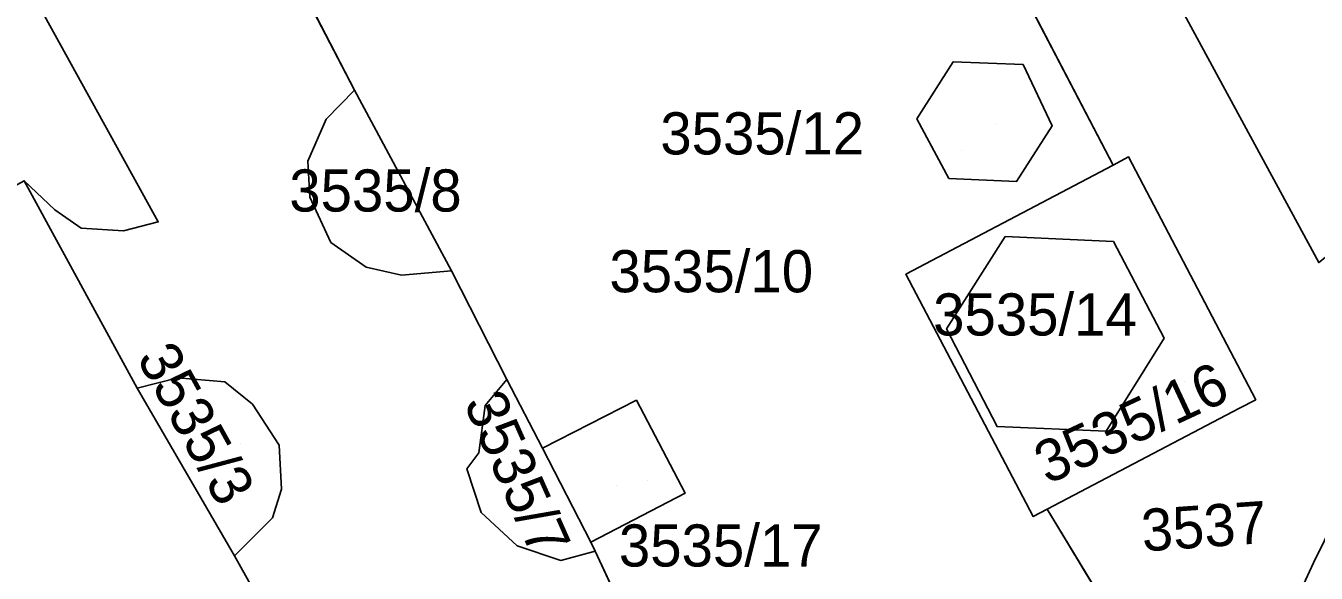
# Model space of a CAD drawing. Extents: x -262715 to -259381, y -1237238 to -1231182.
# Drawn here: x -261483.2 to -261422, y -1235944.4 to -1235918.5 of the extents above; entities that cross this region are included whole.
import ezdxf

# ---------------------------------------------------------------- set-up
doc = ezdxf.new("R2010")
doc.units = 0
for name, color, linetype in [('body_kn', 7, 'Continuous'), ('kladpar_druhypozemkov', 7, 'Continuous'), ('kladpar_hranice', 7, 'Continuous'), ('kladpar_parcelnecisla', 7, 'Continuous'), ('kladpar_plochy', 7, 'Continuous'), ('kladpar_sipky', 7, 'Continuous')]:
    doc.layers.add(name, color=color, linetype=linetype)

msp = doc.modelspace()

# ---------------------------------------------------------------- linework, layer by layer
at = {"layer": 'body_kn'}
for p, q in [((-261439.19, -1235920.17), (-261439.19, -1235920.17)), ((-261435.88, -1235920.3), (-261435.88, -1235920.3)), ((-261435.88, -1235920.3), (-261435.88, -1235920.3)), ((-261467.6, -1235921.52), (-261467.6, -1235921.52)), ((-261467.6, -1235921.52), (-261467.6, -1235921.52)), ((-261468.95, -1235922.89), (-261468.95, -1235922.89)), ((-261440.92, -1235922.88), (-261440.92, -1235922.88)), ((-261434.5, -1235923.21), (-261434.5, -1235923.21)), ((-261469.82, -1235924.89), (-261469.82, -1235924.89)), ((-261430.87, -1235924.69), (-261430.87, -1235924.69)), ((-261431.61, -1235925.08), (-261431.61, -1235925.08)), ((-261439.4, -1235925.71), (-261439.4, -1235925.71)), ((-261436.19, -1235925.85), (-261436.19, -1235925.85)), ((-261469.73, -1235926.59), (-261469.73, -1235926.59)), ((-261481.82, -1235927.19), (-261481.82, -1235927.19)), ((-261480.58, -1235928.07), (-261480.58, -1235928.07)), ((-261476.92, -1235927.77), (-261476.92, -1235927.77)), ((-261478.56, -1235928.2), (-261478.56, -1235928.2)), ((-261436.73, -1235928.47), (-261436.73, -1235928.47)), ((-261436.73, -1235928.47), (-261436.73, -1235928.47)), ((-261431.59, -1235928.7), (-261431.59, -1235928.7)), ((-261468.72, -1235928.74), (-261468.72, -1235928.74)), ((-261467.05, -1235929.91), (-261467.05, -1235929.91)), ((-261465.37, -1235930.3), (-261465.37, -1235930.3)), ((-261463, -1235930.09), (-261463, -1235930.09)), ((-261441.45, -1235930.25), (-261441.45, -1235930.25)), ((-261441.45, -1235930.25), (-261441.45, -1235930.25)), ((-261439.51, -1235932.85), (-261439.51, -1235932.85)), ((-261429.19, -1235933.28), (-261429.19, -1235933.28)), ((-261475.99, -1235935.17), (-261475.99, -1235935.17)), ((-261473.75, -1235935.35), (-261473.75, -1235935.35)), ((-261460.37, -1235935.25), (-261460.37, -1235935.25)), ((-261460.37, -1235935.25), (-261460.37, -1235935.25)), ((-261477.92, -1235935.65), (-261477.92, -1235935.65)), ((-261477.92, -1235935.65), (-261477.92, -1235935.65)), ((-261472.44, -1235936.42), (-261472.44, -1235936.42)), ((-261461.4, -1235936.48), (-261461.4, -1235936.48)), ((-261454.23, -1235936.23), (-261454.23, -1235936.23)), ((-261454.23, -1235936.23), (-261454.23, -1235936.23)), ((-261425.61, -1235936.61), (-261425.61, -1235936.61)), ((-261424.84, -1235936.21), (-261424.84, -1235936.21)), ((-261437.11, -1235937.48), (-261437.11, -1235937.48)), ((-261431.94, -1235937.69), (-261431.94, -1235937.69)), ((-261471.18, -1235938.36), (-261471.18, -1235938.36)), ((-261458.69, -1235938.51), (-261458.69, -1235938.51)), ((-261461.7, -1235938.73), (-261461.7, -1235938.73)), ((-261462.27, -1235939.48), (-261462.27, -1235939.48)), ((-261471.07, -1235940.45), (-261471.07, -1235940.45)), ((-261451.92, -1235940.64), (-261451.92, -1235940.64)), ((-261461.6, -1235941.55), (-261461.6, -1235941.55)), ((-261434.73, -1235941.4), (-261434.73, -1235941.4)), ((-261471.49, -1235941.81), (-261471.49, -1235941.81)), ((-261435.4, -1235941.75), (-261435.4, -1235941.75)), ((-261459.89, -1235943.13), (-261459.89, -1235943.13)), ((-261456.39, -1235942.97), (-261456.39, -1235942.97)), ((-261456.18, -1235943.39), (-261456.18, -1235943.39)), ((-261473.3, -1235943.61), (-261473.3, -1235943.61)), ((-261457.81, -1235943.83), (-261457.81, -1235943.83)), ((-261422.09, -1235943.94), (-261422.09, -1235943.94)), ((-261422.09, -1235943.94), (-261422.09, -1235943.94))]:
    msp.add_line(p, q, dxfattribs=at)
at = {"layer": 'kladpar_druhypozemkov'}
for p, q in [((-261437.13, -1235923.15), (-261437.13, -1235923.15)), ((-261467.72, -1235925.35), (-261467.72, -1235925.35)), ((-261450.39, -1235929.76), (-261450.39, -1235929.76)), ((-261434.27, -1235931.19), (-261434.27, -1235931.19)), ((-261428.22, -1235935.35), (-261428.22, -1235935.35)), ((-261473.01, -1235938.3), (-261473.01, -1235938.3)), ((-261455.19, -1235940.27), (-261455.19, -1235940.27)), ((-261458.4, -1235940.4), (-261458.4, -1235940.4)), ((-261427.52, -1235941.33), (-261427.52, -1235941.33))]:
    msp.add_line(p, q, dxfattribs=at)
at = {"layer": 'kladpar_hranice'}
msp.add_line((-261446.45, -1235896.62), (-261431.61, -1235925.08), dxfattribs=at)
for points in [[(-261437.45, -1235878.07), (-261434.35, -1235876.88), (-261432.22, -1235880.38), (-261431.02, -1235879.92), (-261410.68, -1235917.85), (-261415.58, -1235924.75), (-261421.85, -1235929.7), (-261444.84, -1235887.28), (-261440.59, -1235885.3), (-261443.23, -1235880.49), (-261437.45, -1235878.07)], [(-261430.22, -1235948.85), (-261434.73, -1235941.4), (-261425.61, -1235936.61), (-261424.84, -1235936.21), (-261430.87, -1235924.69), (-261431.61, -1235925.08), (-261446.45, -1235896.62), (-261449.85, -1235890.1), (-261444.84, -1235887.28), (-261421.85, -1235929.7)], [(-261498.26, -1235889.12), (-261476.92, -1235927.77), (-261478.56, -1235928.2), (-261480.58, -1235928.07), (-261481.82, -1235927.19), (-261483.28, -1235925.82)], [(-261470.31, -1235948.96), (-261473.3, -1235943.61), (-261471.49, -1235941.81), (-261471.07, -1235940.45), (-261471.18, -1235938.36), (-261472.44, -1235936.42), (-261473.75, -1235935.35), (-261475.99, -1235935.17), (-261477.92, -1235935.65), (-261483.28, -1235925.82), (-261481.82, -1235927.19), (-261480.58, -1235928.07), (-261478.56, -1235928.2), (-261476.92, -1235927.77), (-261498.26, -1235889.12)], [(-261434.73, -1235941.4), (-261430.22, -1235948.85), (-261434.64, -1235951.63), (-261431.85, -1235956.97), (-261445.42, -1235964.24), (-261447.18, -1235961.03), (-261450.04, -1235955.6), (-261453.49, -1235949.18), (-261456.18, -1235943.39), (-261456.39, -1235942.97), (-261451.92, -1235940.64), (-261454.23, -1235936.23), (-261458.69, -1235938.51), (-261460.37, -1235935.25), (-261463, -1235930.09), (-261467.6, -1235921.52), (-261470.73, -1235915.49), (-261473.34, -1235910.59), (-261446.45, -1235896.62)], [(-261404.6, -1235908.41), (-261402.81, -1235911.43), (-261410.92, -1235928.75), (-261419.45, -1235945.82), (-261426.16, -1235960.39), (-261437.51, -1235985.18), (-261439.52, -1235981.72), (-261422.09, -1235943.94), (-261404.6, -1235908.41)], [(-261404.6, -1235908.41), (-261422.09, -1235943.94)], [(-261470.73, -1235915.49), (-261467.6, -1235921.52), (-261468.95, -1235922.89), (-261469.82, -1235924.89), (-261469.73, -1235926.59), (-261468.72, -1235928.74), (-261467.05, -1235929.91), (-261465.37, -1235930.3), (-261463, -1235930.09), (-261460.37, -1235935.25), (-261461.4, -1235936.48), (-261461.7, -1235938.73), (-261462.27, -1235939.48), (-261461.6, -1235941.55), (-261459.89, -1235943.13), (-261457.81, -1235943.83), (-261456.18, -1235943.39), (-261453.49, -1235949.18)], [(-261435.88, -1235920.3), (-261434.5, -1235923.21), (-261436.19, -1235925.85), (-261439.4, -1235925.71), (-261440.92, -1235922.88), (-261439.19, -1235920.17), (-261435.88, -1235920.3)], [(-261434.5, -1235923.21), (-261435.88, -1235920.3), (-261439.19, -1235920.17), (-261440.92, -1235922.88), (-261439.4, -1235925.71), (-261436.19, -1235925.85), (-261434.5, -1235923.21)], [(-261467.6, -1235921.52), (-261463, -1235930.09), (-261465.37, -1235930.3), (-261467.05, -1235929.91), (-261468.72, -1235928.74), (-261469.73, -1235926.59), (-261469.82, -1235924.89), (-261468.95, -1235922.89), (-261467.6, -1235921.52)], [(-261441.45, -1235930.25), (-261431.61, -1235925.08), (-261430.87, -1235924.69)], [(-261430.87, -1235924.69), (-261424.84, -1235936.21), (-261425.61, -1235936.61), (-261434.73, -1235941.4), (-261435.4, -1235941.75), (-261441.45, -1235930.25)], [(-261431.61, -1235925.08), (-261441.45, -1235930.25), (-261435.4, -1235941.75), (-261434.73, -1235941.4)], [(-261483.28, -1235925.82), (-261477.92, -1235935.65), (-261473.3, -1235943.61), (-261470.31, -1235948.96), (-261465.91, -1235957.36), (-261463.14, -1235963.01), (-261458.68, -1235971.33), (-261455.74, -1235976.71), (-261453.68, -1235980.59), (-261462.01, -1235986.18), (-261466.66, -1235989.3), (-261468.65, -1235990.63), (-261482.76, -1235966.24), (-261488.77, -1235955.11), (-261496.92, -1235940.85), (-261490.32, -1235937.3), (-261493.41, -1235931.37), (-261483.28, -1235925.82)], [(-261436.73, -1235928.47), (-261431.59, -1235928.7), (-261429.19, -1235933.28), (-261431.94, -1235937.69), (-261437.11, -1235937.48), (-261439.51, -1235932.85), (-261436.73, -1235928.47)], [(-261436.73, -1235928.47), (-261439.51, -1235932.85), (-261437.11, -1235937.48), (-261431.94, -1235937.69), (-261429.19, -1235933.28), (-261431.59, -1235928.7), (-261436.73, -1235928.47)], [(-261477.92, -1235935.65), (-261475.99, -1235935.17), (-261473.75, -1235935.35), (-261472.44, -1235936.42), (-261471.18, -1235938.36), (-261471.07, -1235940.45), (-261471.49, -1235941.81), (-261473.3, -1235943.61), (-261477.92, -1235935.65)], [(-261460.37, -1235935.25), (-261458.69, -1235938.51), (-261456.39, -1235942.97), (-261456.18, -1235943.39), (-261457.81, -1235943.83), (-261459.89, -1235943.13), (-261461.6, -1235941.55), (-261462.27, -1235939.48), (-261461.7, -1235938.73), (-261461.4, -1235936.48), (-261460.37, -1235935.25)], [(-261454.23, -1235936.23), (-261451.92, -1235940.64), (-261456.39, -1235942.97), (-261458.69, -1235938.51), (-261454.23, -1235936.23)], [(-261422.09, -1235943.94), (-261439.52, -1235981.72)]]:
    msp.add_lwpolyline(points, dxfattribs=at)
at = {"layer": 'kladpar_plochy'}
for p, q in [((-261446.45, -1235896.62), (-261431.61, -1235925.08)), ((-261467.6, -1235921.52), (-261470.73, -1235915.49)), ((-261439.19, -1235920.17), (-261440.92, -1235922.88)), ((-261435.88, -1235920.3), (-261439.19, -1235920.17)), ((-261434.5, -1235923.21), (-261435.88, -1235920.3)), ((-261463, -1235930.09), (-261467.6, -1235921.52)), ((-261440.92, -1235922.88), (-261439.4, -1235925.71)), ((-261436.19, -1235925.85), (-261434.5, -1235923.21)), ((-261431.61, -1235925.08), (-261430.87, -1235924.69)), ((-261430.87, -1235924.69), (-261424.84, -1235936.21)), ((-261441.45, -1235930.25), (-261431.61, -1235925.08)), ((-261431.61, -1235925.08), (-261441.45, -1235930.25)), ((-261439.4, -1235925.71), (-261436.19, -1235925.85)), ((-261436.73, -1235928.47), (-261439.51, -1235932.85)), ((-261431.59, -1235928.7), (-261436.73, -1235928.47)), ((-261429.19, -1235933.28), (-261431.59, -1235928.7)), ((-261460.37, -1235935.25), (-261463, -1235930.09)), ((-261435.4, -1235941.75), (-261441.45, -1235930.25)), ((-261441.45, -1235930.25), (-261435.4, -1235941.75)), ((-261439.51, -1235932.85), (-261437.11, -1235937.48)), ((-261431.94, -1235937.69), (-261429.19, -1235933.28)), ((-261458.69, -1235938.51), (-261460.37, -1235935.25)), ((-261454.23, -1235936.23), (-261458.69, -1235938.51)), ((-261451.92, -1235940.64), (-261454.23, -1235936.23)), ((-261425.61, -1235936.61), (-261434.73, -1235941.4)), ((-261424.84, -1235936.21), (-261425.61, -1235936.61)), ((-261437.11, -1235937.48), (-261431.94, -1235937.69)), ((-261456.39, -1235942.97), (-261451.92, -1235940.64)), ((-261434.73, -1235941.4), (-261435.4, -1235941.75)), ((-261435.4, -1235941.75), (-261434.73, -1235941.4)), ((-261434.73, -1235941.4), (-261430.22, -1235948.85)), ((-261456.18, -1235943.39), (-261456.39, -1235942.97)), ((-261453.49, -1235949.18), (-261456.18, -1235943.39))]:
    msp.add_line(p, q, dxfattribs=at)
for points in [[(-261437.45, -1235878.07), (-261434.35, -1235876.88), (-261432.22, -1235880.38), (-261431.02, -1235879.92), (-261410.68, -1235917.85), (-261415.58, -1235924.75), (-261421.85, -1235929.7), (-261444.84, -1235887.28), (-261440.59, -1235885.3), (-261443.23, -1235880.49)], [(-261404.6, -1235908.41), (-261402.81, -1235911.43), (-261410.92, -1235928.75), (-261419.45, -1235945.82), (-261426.16, -1235960.39), (-261437.51, -1235985.18), (-261439.52, -1235981.72), (-261422.09, -1235943.94)], [(-261435.88, -1235920.3), (-261434.5, -1235923.21), (-261436.19, -1235925.85), (-261439.4, -1235925.71), (-261440.92, -1235922.88), (-261439.19, -1235920.17)], [(-261467.6, -1235921.52), (-261463, -1235930.09), (-261465.37, -1235930.3), (-261467.05, -1235929.91), (-261468.72, -1235928.74), (-261469.73, -1235926.59), (-261469.82, -1235924.89), (-261468.95, -1235922.89)], [(-261483.28, -1235925.82), (-261477.92, -1235935.65), (-261473.3, -1235943.61), (-261470.31, -1235948.96), (-261465.91, -1235957.36), (-261463.14, -1235963.01), (-261458.68, -1235971.33), (-261455.74, -1235976.71), (-261453.68, -1235980.59), (-261462.01, -1235986.18), (-261466.66, -1235989.3), (-261468.65, -1235990.63), (-261482.76, -1235966.24), (-261488.77, -1235955.11), (-261496.92, -1235940.85), (-261490.32, -1235937.3), (-261493.41, -1235931.37)], [(-261436.73, -1235928.47), (-261431.59, -1235928.7), (-261429.19, -1235933.28), (-261431.94, -1235937.69), (-261437.11, -1235937.48), (-261439.51, -1235932.85)], [(-261477.92, -1235935.65), (-261475.99, -1235935.17), (-261473.75, -1235935.35), (-261472.44, -1235936.42), (-261471.18, -1235938.36), (-261471.07, -1235940.45), (-261471.49, -1235941.81), (-261473.3, -1235943.61)], [(-261460.37, -1235935.25), (-261458.69, -1235938.51), (-261456.39, -1235942.97), (-261456.18, -1235943.39), (-261457.81, -1235943.83), (-261459.89, -1235943.13), (-261461.6, -1235941.55), (-261462.27, -1235939.48), (-261461.7, -1235938.73), (-261461.4, -1235936.48)], [(-261454.23, -1235936.23), (-261451.92, -1235940.64), (-261456.39, -1235942.97), (-261458.69, -1235938.51)]]:
    msp.add_lwpolyline(points, close=True, dxfattribs=at)
for points in [[(-261430.22, -1235948.85), (-261434.73, -1235941.4), (-261425.61, -1235936.61), (-261424.84, -1235936.21), (-261430.87, -1235924.69), (-261431.61, -1235925.08), (-261446.45, -1235896.62), (-261449.85, -1235890.1), (-261444.84, -1235887.28), (-261421.85, -1235929.7)], [(-261498.26, -1235889.12), (-261476.92, -1235927.77), (-261478.56, -1235928.2), (-261480.58, -1235928.07), (-261481.82, -1235927.19), (-261483.28, -1235925.82)], [(-261470.31, -1235948.96), (-261473.3, -1235943.61), (-261471.49, -1235941.81), (-261471.07, -1235940.45), (-261471.18, -1235938.36), (-261472.44, -1235936.42), (-261473.75, -1235935.35), (-261475.99, -1235935.17), (-261477.92, -1235935.65), (-261483.28, -1235925.82), (-261481.82, -1235927.19), (-261480.58, -1235928.07), (-261478.56, -1235928.2), (-261476.92, -1235927.77), (-261498.26, -1235889.12)], [(-261404.6, -1235908.41), (-261422.09, -1235943.94), (-261439.52, -1235981.72)], [(-261470.73, -1235915.49), (-261467.6, -1235921.52), (-261468.95, -1235922.89), (-261469.82, -1235924.89), (-261469.73, -1235926.59), (-261468.72, -1235928.74), (-261467.05, -1235929.91), (-261465.37, -1235930.3), (-261463, -1235930.09), (-261460.37, -1235935.25), (-261461.4, -1235936.48), (-261461.7, -1235938.73), (-261462.27, -1235939.48), (-261461.6, -1235941.55), (-261459.89, -1235943.13), (-261457.81, -1235943.83), (-261456.18, -1235943.39), (-261453.49, -1235949.18)]]:
    msp.add_lwpolyline(points, dxfattribs=at)
at = {"layer": 'kladpar_sipky'}
for p, q in [((-261438.81, -1235924.4), (-261438.81, -1235924.4)), ((-261453.69, -1235940.05), (-261453.69, -1235940.05))]:
    msp.add_line(p, q, dxfattribs=at)

# ---------------------------------------------------------------- texts
at = {"layer": 'kladpar_parcelnecisla'}
for s, p in [('3535/12', (-261453.093, -1235924.57)), ('3535/8', (-261470.699, -1235927.28)), ('3535/10', (-261455.508, -1235931.11)), ('3535/14', (-261440.147, -1235933.16)), ('3535/17', (-261455.059, -1235944.12))]:
    msp.add_text(s, height=2, dxfattribs=at).set_placement(p)
for s, rotation, p in [('3535/3', 299, (-261477.968, -1235934.228)), ('3535/16', 25, (-261434.722, -1235940.249)), ('3535/7', 294, (-261462.445, -1235936.361)), ('3537', 4, (-261430.195, -1235943.409))]:
    msp.add_text(s, height=2, rotation=rotation, dxfattribs=at).set_placement(p)

doc.saveas('drawing.dxf')
